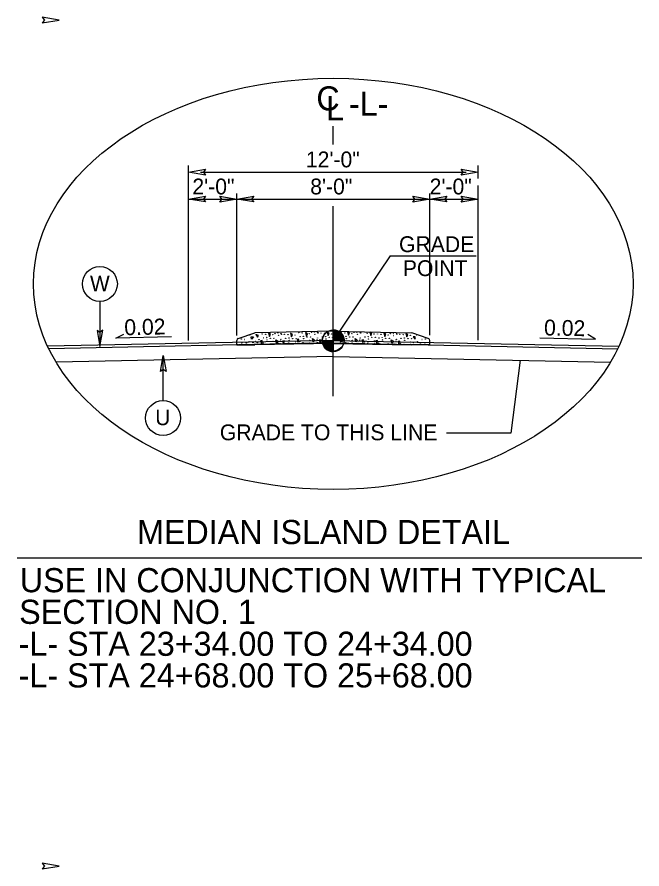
# Model space of a CAD drawing. Extents: x 1901718 to 1902220, y 193828 to 194187.
# Drawn here: x 1901932.98 to 1901958.87, y 194045.94 to 194081.24 of the extents above; entities that cross this region are included whole.
import ezdxf

# ---------------------------------------------------------------- set-up
doc = ezdxf.new("R2010")
doc.units = 0
for name, color, linetype in [('Old_Level_1', 7, 'Continuous'), ('Old_Level_11', 7, 'Continuous'), ('Old_Level_19', 7, 'Continuous'), ('Old_Level_2', 7, 'Continuous'), ('Old_Level_20', 7, 'Continuous'), ('Old_Level_3', 7, 'Continuous'), ('Prop Dimension', 7, 'Continuous'), ('Typical Curb CELL', 7, 'Continuous'), ('Typical Terminator CELL', 7, 'Continuous')]:
    doc.layers.add(name, color=color, linetype=linetype)

# ---------------------------------------------------------------- blocks, each defined once
blk = doc.blocks.new('TERMINATOR')
at = {"layer": 'Typical Terminator CELL'}
blk.add_lwpolyline([(-0.469, 0.081), (0, 0), (-0.471, -0.083), (-0.411, 0)], close=True, dxfattribs=at)

msp = doc.modelspace()

# ---------------------------------------------------------------- linework, layer by layer
at = {"layer": 'Old_Level_1'}
for p, q in [((1901946.083, 194075.955), (1901946.083, 194076.723)), ((1901946.083, 194065.532), (1901946.083, 194073.405)), ((1901946.083, 194067.838), (1901946.083, 194068.279)), ((1901946.083, 194067.828), (1901946.083, 194068.278)), ((1901946.083, 194067.838), (1901934.243, 194067.601)), ((1901937.074, 194067.936), (1901937.407, 194068.103)), ((1901939.378, 194067.984), (1901937.074, 194067.936)), ((1901945.633, 194067.828), (1901946.083, 194067.828)), ((1901945.642, 194067.838), (1901946.083, 194067.838)), ((1901946.082, 194067.397), (1901946.083, 194067.838)), ((1901946.083, 194067.838), (1901946.082, 194067.397)), ((1901946.082, 194067.378), (1901946.083, 194067.828)), ((1901946.083, 194067.828), (1901946.082, 194067.378)), ((1901946.083, 194067.838), (1901957.922, 194067.601)), ((1901946.524, 194067.838), (1901946.083, 194067.838)), ((1901946.533, 194067.828), (1901946.083, 194067.828)), ((1901954.646, 194067.941), (1901956.95, 194067.893)), ((1901956.95, 194067.893), (1901956.627, 194068.079)), ((1901946.083, 194067.734), (1901934.292, 194067.498)), ((1901946.083, 194067.734), (1901957.874, 194067.498)), ((1901946.083, 194067.172), (1901934.593, 194066.942)), ((1901946.083, 194067.172), (1901957.572, 194066.942))]:
    msp.add_line(p, q, dxfattribs=at)
for points in [[(1901946.087, 194068.279), (1901946.087, 194068.279), (1901946.087, 194067.838)], [(1901946.087, 194068.278), (1901946.087, 194068.278), (1901946.087, 194067.828)], [(1901946.096, 194068.279), (1901946.096, 194067.838)], [(1901946.096, 194068.278), (1901946.096, 194067.828)], [(1901946.104, 194068.278), (1901946.104, 194067.838)], [(1901946.105, 194068.277), (1901946.105, 194067.828)], [(1901946.113, 194068.278), (1901946.113, 194067.838)], [(1901946.114, 194068.277), (1901946.114, 194067.828)], [(1901946.122, 194068.277), (1901946.122, 194067.838)], [(1901946.123, 194068.276), (1901946.123, 194067.828)], [(1901946.131, 194068.276), (1901946.131, 194067.838)], [(1901946.132, 194068.275), (1901946.132, 194067.828)], [(1901946.14, 194068.275), (1901946.14, 194067.838)], [(1901946.141, 194068.274), (1901946.141, 194067.828)], [(1901946.149, 194068.274), (1901946.149, 194067.838)], [(1901946.15, 194068.273), (1901946.15, 194067.828)], [(1901946.157, 194068.273), (1901946.157, 194067.838)], [(1901946.159, 194068.272), (1901946.159, 194067.828)], [(1901946.166, 194068.271), (1901946.166, 194067.838)], [(1901946.168, 194068.27), (1901946.168, 194067.828)], [(1901946.175, 194068.269), (1901946.175, 194067.838)], [(1901946.177, 194068.268), (1901946.177, 194067.828)], [(1901946.184, 194068.267), (1901946.184, 194067.838)], [(1901946.186, 194068.266), (1901946.186, 194067.828)], [(1901946.193, 194068.265), (1901946.193, 194067.838)], [(1901946.195, 194068.264), (1901946.195, 194067.828)], [(1901946.201, 194068.262), (1901946.201, 194067.838)], [(1901946.204, 194068.261), (1901946.204, 194067.828)], [(1901946.21, 194068.26), (1901946.21, 194067.838)], [(1901946.213, 194068.259), (1901946.213, 194067.828)], [(1901946.219, 194068.257), (1901946.219, 194067.838)], [(1901946.222, 194068.256), (1901946.222, 194067.828)], [(1901946.228, 194068.254), (1901946.228, 194067.838)], [(1901946.231, 194068.253), (1901946.231, 194067.828)], [(1901946.237, 194068.251), (1901946.237, 194067.838)], [(1901946.24, 194068.25), (1901946.24, 194067.828)], [(1901946.246, 194068.247), (1901946.246, 194067.838)], [(1901946.249, 194068.246), (1901946.249, 194067.828)], [(1901946.254, 194068.243), (1901946.254, 194067.838)], [(1901946.258, 194068.242), (1901946.258, 194067.828)], [(1901946.263, 194068.239), (1901946.263, 194067.838)], [(1901946.267, 194068.238), (1901946.267, 194067.828)], [(1901946.272, 194068.236), (1901946.272, 194067.838)], [(1901946.276, 194068.234), (1901946.276, 194067.828)], [(1901946.281, 194068.232), (1901946.281, 194067.838)], [(1901946.285, 194068.23), (1901946.285, 194067.828)], [(1901946.29, 194068.227), (1901946.29, 194067.838)], [(1901946.294, 194068.225), (1901946.294, 194067.828)], [(1901946.298, 194068.222), (1901946.298, 194067.838)], [(1901946.303, 194068.22), (1901946.303, 194067.828)], [(1901946.307, 194068.217), (1901946.307, 194067.838)], [(1901946.312, 194068.215), (1901946.312, 194067.828)], [(1901946.316, 194068.212), (1901946.316, 194067.838)], [(1901946.321, 194068.21), (1901946.321, 194067.828)], [(1901946.325, 194068.206), (1901946.325, 194067.838)], [(1901946.33, 194068.204), (1901946.33, 194067.828)], [(1901946.334, 194068.2), (1901946.334, 194067.838)], [(1901946.339, 194068.198), (1901946.339, 194067.828)], [(1901946.343, 194068.193), (1901946.343, 194067.838)], [(1901946.348, 194068.191), (1901946.348, 194067.828)], [(1901946.351, 194068.188), (1901946.351, 194067.838)], [(1901946.357, 194068.185), (1901946.357, 194067.828)], [(1901946.36, 194068.181), (1901946.36, 194067.838)], [(1901945.635, 194067.828), (1901945.635, 194067.779)], [(1901945.644, 194067.838), (1901945.644, 194067.79)], [(1901945.644, 194067.828), (1901945.644, 194067.726)], [(1901945.653, 194067.838), (1901945.653, 194067.738)], [(1901945.653, 194067.828), (1901945.653, 194067.694)], [(1901945.661, 194067.838), (1901945.661, 194067.706)], [(1901945.662, 194067.828), (1901945.662, 194067.667)], [(1901945.67, 194067.838), (1901945.67, 194067.68)], [(1901945.671, 194067.828), (1901945.671, 194067.646)], [(1901945.679, 194067.838), (1901945.679, 194067.659)], [(1901945.68, 194067.828), (1901945.68, 194067.627)], [(1901945.688, 194067.838), (1901945.688, 194067.641)], [(1901945.689, 194067.828), (1901945.689, 194067.61)], [(1901945.697, 194067.838), (1901945.697, 194067.624)], [(1901945.698, 194067.828), (1901945.698, 194067.594)], [(1901945.706, 194067.838), (1901945.706, 194067.608)], [(1901945.707, 194067.828), (1901945.707, 194067.58)], [(1901945.714, 194067.838), (1901945.714, 194067.595)], [(1901945.716, 194067.828), (1901945.716, 194067.567)], [(1901945.723, 194067.838), (1901945.723, 194067.582)], [(1901945.725, 194067.828), (1901945.725, 194067.555)], [(1901945.732, 194067.838), (1901945.732, 194067.57)], [(1901945.734, 194067.828), (1901945.734, 194067.544)], [(1901945.741, 194067.838), (1901945.741, 194067.559)], [(1901945.743, 194067.828), (1901945.743, 194067.533)], [(1901945.75, 194067.838), (1901945.75, 194067.549)], [(1901945.752, 194067.828), (1901945.752, 194067.523)], [(1901945.758, 194067.838), (1901945.758, 194067.539)], [(1901945.761, 194067.828), (1901945.761, 194067.513)], [(1901945.767, 194067.838), (1901945.767, 194067.529)], [(1901945.77, 194067.828), (1901945.77, 194067.504)], [(1901945.776, 194067.838), (1901945.776, 194067.52)], [(1901945.779, 194067.828), (1901945.779, 194067.496)], [(1901945.785, 194067.838), (1901945.785, 194067.512)], [(1901945.788, 194067.828), (1901945.788, 194067.488)], [(1901945.794, 194067.838), (1901945.794, 194067.504)], [(1901945.797, 194067.828), (1901945.797, 194067.48)], [(1901945.803, 194067.838), (1901945.803, 194067.497)], [(1901945.806, 194067.828), (1901945.806, 194067.473)], [(1901945.811, 194067.838), (1901945.811, 194067.49)], [(1901945.815, 194067.828), (1901945.815, 194067.466)], [(1901945.82, 194067.838), (1901945.82, 194067.483)], [(1901945.824, 194067.828), (1901945.824, 194067.46)], [(1901945.829, 194067.838), (1901945.829, 194067.477)], [(1901945.833, 194067.828), (1901945.833, 194067.454)], [(1901945.838, 194067.838), (1901945.838, 194067.471)], [(1901945.842, 194067.828), (1901945.842, 194067.448)], [(1901945.847, 194067.838), (1901945.847, 194067.465)], [(1901945.851, 194067.828), (1901945.851, 194067.442)], [(1901945.856, 194067.838), (1901945.856, 194067.459)], [(1901945.86, 194067.828), (1901945.86, 194067.437)], [(1901945.864, 194067.838), (1901945.864, 194067.454)], [(1901945.869, 194067.828), (1901945.869, 194067.432)], [(1901945.873, 194067.838), (1901945.873, 194067.45)], [(1901945.878, 194067.828), (1901945.878, 194067.427)], [(1901945.882, 194067.838), (1901945.882, 194067.445)], [(1901945.887, 194067.828), (1901945.887, 194067.423)], [(1901945.891, 194067.838), (1901945.891, 194067.441)], [(1901945.896, 194067.828), (1901945.896, 194067.419)], [(1901945.9, 194067.838), (1901945.9, 194067.437)], [(1901945.905, 194067.828), (1901945.905, 194067.415)], [(1901945.908, 194067.838), (1901945.908, 194067.433)], [(1901945.914, 194067.828), (1901945.914, 194067.411)], [(1901945.917, 194067.838), (1901945.917, 194067.429)], [(1901945.923, 194067.828), (1901945.923, 194067.407)], [(1901945.926, 194067.838), (1901945.926, 194067.425)], [(1901945.932, 194067.828), (1901945.932, 194067.404)], [(1901945.935, 194067.838), (1901945.935, 194067.422)], [(1901945.941, 194067.828), (1901945.941, 194067.401)], [(1901945.944, 194067.838), (1901945.944, 194067.419)], [(1901945.95, 194067.828), (1901945.95, 194067.398)], [(1901945.953, 194067.838), (1901945.953, 194067.416)], [(1901945.959, 194067.828), (1901945.959, 194067.396)], [(1901945.961, 194067.838), (1901945.961, 194067.414)], [(1901945.968, 194067.828), (1901945.968, 194067.393)], [(1901945.97, 194067.838), (1901945.97, 194067.411)], [(1901945.977, 194067.828), (1901945.977, 194067.391)], [(1901945.979, 194067.838), (1901945.979, 194067.409)], [(1901945.986, 194067.828), (1901945.986, 194067.389)], [(1901945.988, 194067.838), (1901945.988, 194067.407)], [(1901945.995, 194067.828), (1901945.995, 194067.387)], [(1901945.997, 194067.838), (1901945.997, 194067.405)], [(1901946.004, 194067.828), (1901946.004, 194067.385)], [(1901946.005, 194067.838), (1901946.005, 194067.404)], [(1901946.013, 194067.828), (1901946.013, 194067.384)], [(1901946.014, 194067.838), (1901946.014, 194067.403)], [(1901946.022, 194067.828), (1901946.022, 194067.382)], [(1901946.023, 194067.838), (1901946.023, 194067.401)], [(1901946.031, 194067.828), (1901946.031, 194067.381)], [(1901946.032, 194067.838), (1901946.032, 194067.4)], [(1901946.04, 194067.828), (1901946.04, 194067.38)], [(1901946.041, 194067.838), (1901946.041, 194067.399)], [(1901946.049, 194067.828), (1901946.049, 194067.379)], [(1901946.05, 194067.838), (1901946.05, 194067.398)], [(1901946.058, 194067.838), (1901946.058, 194067.398)], [(1901946.058, 194067.828), (1901946.058, 194067.379)], [(1901946.067, 194067.838), (1901946.067, 194067.397)], [(1901946.067, 194067.828), (1901946.067, 194067.378)], [(1901946.076, 194067.838), (1901946.076, 194067.397), (1901946.076, 194067.397)], [(1901946.076, 194067.828), (1901946.076, 194067.378), (1901946.076, 194067.378)], [(1901946.366, 194068.178), (1901946.366, 194067.828)], [(1901946.369, 194068.173), (1901946.369, 194067.838)], [(1901946.375, 194068.17), (1901946.375, 194067.828)], [(1901946.378, 194068.165), (1901946.378, 194067.838)], [(1901946.384, 194068.162), (1901946.384, 194067.828)], [(1901946.387, 194068.157), (1901946.387, 194067.838)], [(1901946.393, 194068.154), (1901946.393, 194067.828)], [(1901946.395, 194068.148), (1901946.395, 194067.838)], [(1901946.402, 194068.145), (1901946.402, 194067.828)], [(1901946.404, 194068.139), (1901946.404, 194067.838)], [(1901946.411, 194068.136), (1901946.411, 194067.828)], [(1901946.413, 194068.13), (1901946.413, 194067.838)], [(1901946.42, 194068.126), (1901946.42, 194067.828)], [(1901946.422, 194068.119), (1901946.422, 194067.838)], [(1901946.429, 194068.115), (1901946.429, 194067.828)], [(1901946.431, 194068.108), (1901946.431, 194067.838)], [(1901946.438, 194068.104), (1901946.438, 194067.828)], [(1901946.44, 194068.096), (1901946.44, 194067.838)], [(1901946.447, 194068.092), (1901946.447, 194067.828)], [(1901946.448, 194068.084), (1901946.448, 194067.838)], [(1901946.456, 194068.079), (1901946.456, 194067.828)], [(1901946.457, 194068.07), (1901946.457, 194067.838)], [(1901946.465, 194068.065), (1901946.465, 194067.828)], [(1901946.466, 194068.055), (1901946.466, 194067.838)], [(1901946.474, 194068.05), (1901946.474, 194067.828)], [(1901946.475, 194068.04), (1901946.475, 194067.838)], [(1901946.483, 194068.034), (1901946.483, 194067.828)], [(1901946.484, 194068.021), (1901946.484, 194067.838)], [(1901946.492, 194068.015), (1901946.492, 194067.828)], [(1901946.493, 194068), (1901946.493, 194067.838)], [(1901946.501, 194067.994), (1901946.501, 194067.828)], [(1901946.501, 194067.976), (1901946.501, 194067.838)], [(1901946.51, 194067.969), (1901946.51, 194067.828)], [(1901946.51, 194067.945), (1901946.51, 194067.838)], [(1901946.519, 194067.938), (1901946.519, 194067.828)], [(1901946.519, 194067.9), (1901946.519, 194067.838)], [(1901946.528, 194067.892), (1901946.528, 194067.828)], [(1901953.827, 194067.02), (1901953.441, 194064.001), (1901950.774, 194064.001)]]:
    msp.add_lwpolyline(points, dxfattribs=at)
for centre, radius in [((1901946.082, 194067.828), 0.45), ((1901946.082, 194067.838), 0.441)]:
    msp.add_circle(centre, radius, dxfattribs=at)
for centre, radius, start, end in [((1901946.082, 194067.838), 0.441, 359.9905, 89.9905), ((1901946.082, 194067.828), 0.45, 359.9905, 89.9905), ((1901946.082, 194067.828), 0.45, 179.9905, 269.9905), ((1901946.082, 194067.838), 0.441, 179.9905, 269.9905)]:
    msp.add_arc(centre, radius, start, end, dxfattribs=at)
at = {"layer": 'Old_Level_11'}
for p, q in [((1901936.409, 194069.458), (1901936.409, 194067.584)), ((1901939.031, 194065.347), (1901939.031, 194067.221)), ((1901932.977, 194058.837), (1901958.875, 194058.837))]:
    msp.add_line(p, q, dxfattribs=at)
for points in [[(1901936.293, 194068.255), (1901936.409, 194067.584), (1901936.528, 194068.259), (1901936.409, 194068.173)], [(1901938.916, 194066.549), (1901939.031, 194067.221), (1901939.151, 194066.546), (1901939.031, 194066.631)]]:
    msp.add_lwpolyline(points, close=True, dxfattribs=at)
for centre in [(1901936.409, 194070.183), (1901939.031, 194064.621)]:
    msp.add_circle(centre, 0.725, dxfattribs=at)
at = {"layer": 'Old_Level_3'}
for q in [(1901946.083, 194067.838), (1901951.998, 194071.342)]:
    msp.add_line((1901948.434, 194071.342), q, dxfattribs=at)
at = {"layer": 'Prop Dimension'}
for p, q in [((1901940.083, 194067.843), (1901940.083, 194075.089)), ((1901952.083, 194074.55), (1901952.083, 194075.089)), ((1901940.583, 194074.814), (1901951.583, 194074.814)), ((1901952.083, 194067.85), (1901952.083, 194074.266)), ((1901942.083, 194068.047), (1901942.083, 194073.931)), ((1901950.083, 194068.055), (1901950.083, 194073.931)), ((1901940.083, 194073.699), (1901942.083, 194073.699)), ((1901942.083, 194073.699), (1901950.083, 194073.699)), ((1901950.083, 194073.699), (1901952.083, 194073.699))]:
    msp.add_line(p, q, dxfattribs=at)
at = {"layer": 'Typical Curb CELL'}
for p, q in [((1901946.083, 194068.219), (1901942.833, 194068.154)), ((1901945.831, 194068.186), (1901945.872, 194068.038)), ((1901945.913, 194068.128), (1901945.831, 194068.186)), ((1901946.083, 194068.219), (1901949.333, 194068.154)), ((1901946.677, 194068.202), (1901946.719, 194068.053)), ((1901946.76, 194068.144), (1901946.677, 194068.202)), ((1901947.597, 194068.186), (1901947.638, 194068.038)), ((1901947.679, 194068.128), (1901947.597, 194068.186)), ((1901942.083, 194067.831), (1901942.083, 194067.836)), ((1901942.083, 194067.654), (1901942.083, 194067.836)), ((1901942.147, 194067.925), (1901942.833, 194068.154)), ((1901942.686, 194067.982), (1901942.772, 194067.982)), ((1901942.69, 194067.896), (1901942.686, 194067.982)), ((1901942.772, 194067.982), (1901942.69, 194067.896)), ((1901942.977, 194068.044), (1901942.867, 194068.079)), ((1901942.867, 194068.079), (1901942.945, 194067.978)), ((1901942.945, 194067.978), (1901942.977, 194068.044)), ((1901943.138, 194067.834), (1901943.066, 194067.821)), ((1901943.103, 194067.712), (1901943.138, 194067.834)), ((1901943.396, 194068.15), (1901943.437, 194068.001)), ((1901943.478, 194068.092), (1901943.396, 194068.15)), ((1901943.437, 194068.001), (1901943.478, 194068.092)), ((1901943.703, 194067.861), (1901943.793, 194067.812)), ((1901943.735, 194067.731), (1901943.703, 194067.861)), ((1901944.315, 194068.134), (1901944.356, 194067.986)), ((1901944.397, 194068.076), (1901944.315, 194068.134)), ((1901944.356, 194067.986), (1901944.397, 194068.076)), ((1901944.654, 194067.886), (1901944.582, 194067.873)), ((1901944.582, 194067.873), (1901944.619, 194067.764)), ((1901944.619, 194067.764), (1901944.654, 194067.886)), ((1901944.934, 194068.168), (1901944.976, 194068.019)), ((1901945.016, 194068.11), (1901944.934, 194068.168)), ((1901944.976, 194068.019), (1901945.016, 194068.11)), ((1901945.219, 194067.913), (1901945.309, 194067.864)), ((1901945.251, 194067.783), (1901945.219, 194067.913)), ((1901945.309, 194067.864), (1901945.251, 194067.783)), ((1901945.574, 194067.871), (1901945.501, 194067.857)), ((1901945.501, 194067.857), (1901945.538, 194067.748)), ((1901945.538, 194067.748), (1901945.574, 194067.871)), ((1901945.872, 194068.038), (1901945.913, 194068.128)), ((1901946.42, 194067.886), (1901946.348, 194067.873)), ((1901946.348, 194067.873), (1901946.385, 194067.764)), ((1901946.385, 194067.764), (1901946.42, 194067.886)), ((1901946.719, 194068.053), (1901946.76, 194068.144)), ((1901946.985, 194067.913), (1901947.075, 194067.864)), ((1901947.017, 194067.783), (1901946.985, 194067.913)), ((1901947.075, 194067.864), (1901947.017, 194067.783)), ((1901947.339, 194067.871), (1901947.267, 194067.857)), ((1901947.267, 194067.857), (1901947.304, 194067.748)), ((1901947.304, 194067.748), (1901947.339, 194067.871)), ((1901947.638, 194068.038), (1901947.679, 194068.128)), ((1901947.919, 194067.832), (1901947.847, 194067.818)), ((1901947.883, 194067.709), (1901947.919, 194067.832)), ((1901948.176, 194068.148), (1901948.218, 194067.998)), ((1901948.258, 194068.089), (1901948.176, 194068.148)), ((1901948.218, 194067.998), (1901948.258, 194068.089)), ((1901948.484, 194067.859), (1901948.574, 194067.809)), ((1901948.516, 194067.728), (1901948.484, 194067.859)), ((1901949.095, 194068.132), (1901949.137, 194067.983)), ((1901949.177, 194068.073), (1901949.095, 194068.132)), ((1901949.137, 194067.983), (1901949.177, 194068.073)), ((1901950.019, 194067.925), (1901949.333, 194068.154)), ((1901949.48, 194067.982), (1901949.394, 194067.982)), ((1901949.394, 194067.982), (1901949.475, 194067.896)), ((1901949.475, 194067.896), (1901949.48, 194067.982)), ((1901950.083, 194067.831), (1901950.083, 194067.836)), ((1901950.083, 194067.654), (1901950.083, 194067.836)), ((1901942.083, 194067.654), (1901942.833, 194067.654)), ((1901946.083, 194067.719), (1901942.833, 194067.654)), ((1901943.066, 194067.821), (1901943.103, 194067.712)), ((1901943.793, 194067.812), (1901943.735, 194067.731)), ((1901944.058, 194067.819), (1901943.985, 194067.805)), ((1901943.985, 194067.805), (1901944.022, 194067.696)), ((1901944.022, 194067.696), (1901944.058, 194067.819)), ((1901946.083, 194067.719), (1901949.333, 194067.654)), ((1901947.847, 194067.818), (1901947.883, 194067.709)), ((1901948.574, 194067.809), (1901948.516, 194067.728)), ((1901948.838, 194067.816), (1901948.766, 194067.802)), ((1901948.766, 194067.802), (1901948.802, 194067.693)), ((1901948.802, 194067.693), (1901948.838, 194067.816)), ((1901950.083, 194067.654), (1901949.333, 194067.654))]:
    msp.add_line(p, q, dxfattribs=at)
for centre in [(1901945.301, 194068.187), (1901945.436, 194068.175), (1901947.202, 194068.175), (1901942.27, 194067.901), (1901942.406, 194067.878), (1901942.623, 194068.068), (1901943.004, 194067.867), (1901943.134, 194068.105), (1901943.193, 194067.947), (1901943.283, 194068.091), (1901943.328, 194067.96), (1901943.342, 194067.865), (1901943.478, 194067.929), (1901943.572, 194068.073), (1901943.622, 194067.933), (1901943.663, 194068.119), (1901943.785, 194068.146), (1901943.807, 194068.046), (1901943.913, 194067.891), (1901943.92, 194068.123), (1901943.936, 194068.094), (1901944.053, 194068.089), (1901944.112, 194067.931), (1901944.202, 194068.076), (1901944.248, 194067.945), (1901944.261, 194067.85), (1901944.397, 194067.913), (1901944.492, 194068.058), (1901944.541, 194067.918), (1901944.65, 194068.157), (1901944.709, 194067.999), (1901944.799, 194068.143), (1901944.845, 194068.012), (1901944.858, 194067.917), (1901944.994, 194067.981), (1901945.088, 194068.125), (1901945.107, 194067.85), (1901945.138, 194067.985), (1901945.179, 194068.171), (1901945.323, 194068.098), (1901945.414, 194067.863), (1901945.429, 194067.943), (1901945.452, 194068.146), (1901945.569, 194068.141), (1901945.628, 194067.983), (1901945.718, 194068.128), (1901945.764, 194067.997), (1901945.777, 194067.902), (1901945.913, 194067.965), (1901946.008, 194068.11), (1901946.026, 194067.834), (1901946.057, 194067.97), (1901946.416, 194068.157), (1901946.475, 194067.999), (1901946.565, 194068.143), (1901946.61, 194068.012), (1901946.624, 194067.917), (1901946.759, 194067.981), (1901946.854, 194068.125), (1901946.872, 194067.85), (1901946.904, 194067.985), (1901946.945, 194068.171), (1901947.06, 194068.172), (1901947.089, 194068.098), (1901947.179, 194067.863), (1901947.195, 194067.943), (1901947.218, 194068.146), (1901947.335, 194068.141), (1901947.394, 194067.983), (1901947.484, 194068.128), (1901947.529, 194067.997), (1901947.543, 194067.902), (1901947.679, 194067.965), (1901947.773, 194068.11), (1901947.791, 194067.834), (1901947.823, 194067.97), (1901947.915, 194068.102), (1901947.973, 194067.944), (1901948.064, 194068.089), (1901948.109, 194067.958), (1901948.123, 194067.863), (1901948.258, 194067.926), (1901948.353, 194068.071), (1901948.403, 194067.931), (1901948.443, 194068.116), (1901948.565, 194068.143), (1901948.588, 194068.044), (1901948.694, 194067.888), (1901948.701, 194068.121), (1901948.716, 194068.091), (1901948.834, 194068.087), (1901948.893, 194067.929), (1901948.983, 194068.073), (1901949.028, 194067.942), (1901949.042, 194067.847), (1901949.177, 194067.911), (1901949.272, 194068.055), (1901949.322, 194067.915), (1901949.543, 194068.068), (1901949.76, 194067.878), (1901949.896, 194067.901), (1901942.099, 194067.675), (1901942.288, 194067.738), (1901942.478, 194067.733), (1901942.595, 194067.783), (1901942.758, 194067.743), (1901942.85, 194067.795), (1901942.935, 194067.75), (1901943.17, 194067.734), (1901943.315, 194067.694), (1901943.577, 194067.676), (1901943.59, 194067.798), (1901943.821, 194067.723), (1901943.898, 194067.811), (1901943.898, 194067.71), (1901944.089, 194067.719), (1901944.234, 194067.73), (1901944.496, 194067.712), (1901944.51, 194067.782), (1901944.686, 194067.786), (1901944.831, 194067.746), (1901945.093, 194067.728), (1901945.337, 194067.723), (1901945.414, 194067.762), (1901945.606, 194067.771), (1901945.75, 194067.73), (1901946.012, 194067.712), (1901946.452, 194067.786), (1901946.597, 194067.746), (1901946.859, 194067.728), (1901947.103, 194067.723), (1901947.179, 194067.71), (1901947.371, 194067.771), (1901947.516, 194067.73), (1901947.778, 194067.712), (1901947.951, 194067.732), (1901948.095, 194067.691), (1901948.357, 194067.7), (1901948.371, 194067.795), (1901948.601, 194067.695), (1901948.678, 194067.809), (1901948.678, 194067.682), (1901948.87, 194067.716), (1901949.015, 194067.676), (1901949.277, 194067.684), (1901949.29, 194067.78), (1901949.408, 194067.743), (1901949.57, 194067.783), (1901949.688, 194067.733), (1901949.877, 194067.738), (1901950.067, 194067.675)]:
    msp.add_circle(centre, 0.00635, dxfattribs=at)
for centre, start, end in [((1901942.177, 194067.836), 108.435, 180), ((1901949.989, 194067.836), 360, 71.565)]:
    msp.add_arc(centre, 0.0937, start, end, dxfattribs=at)
msp.add_ellipse((1901946.083, 194070.183), major_axis=(12.424, 0), ratio=0.68563, dxfattribs=at)

# ---------------------------------------------------------------- block references
at = {"layer": 'Old_Level_1', "xscale": 1.5, "yscale": -1.5}
for p in [(1901934.727, 194081.116), (1901934.727, 194046.059)]:
    msp.add_blockref('TERMINATOR', p, dxfattribs=at)
at = {"layer": 'Prop Dimension', "xscale": 1.5, "yscale": 1.5, "rotation": 180}
for p in [(1901940.083, 194074.814), (1901940.083, 194073.699), (1901942.083, 194073.699), (1901950.083, 194073.699)]:
    msp.add_blockref('TERMINATOR', p, dxfattribs=at)
at = {"layer": 'Prop Dimension', "xscale": 1.5, "yscale": 1.5}
for p in [(1901952.083, 194074.814), (1901942.083, 194073.699), (1901950.083, 194073.699), (1901952.083, 194073.699)]:
    msp.add_blockref('TERMINATOR', p, dxfattribs=at)

# ---------------------------------------------------------------- texts
at = {"layer": 'Old_Level_1'}
msp.add_text('GRADE TO THIS LINE', height=0.656, dxfattribs=at).set_placement((1901941.381, 194063.702))
at = {"layer": 'Old_Level_19'}
for s, p in [('MEDIAN ISLAND DETAIL', (1901937.95, 194059.4)), ('USE IN CONJUNCTION WITH TYPICAL ', (1901933.091, 194057.405)), ('SECTION NO. 1', (1901933.066, 194056.094)), ('-L- STA 23+34.00 TO 24+34.00', (1901933.047, 194054.77)), ('-L- STA 24+68.00 TO 25+68.00', (1901933.047, 194053.459))]:
    msp.add_text(s, height=1, dxfattribs=at).set_placement(p)
at = {"layer": 'Old_Level_2'}
msp.add_text('C', height=1, dxfattribs=at).set_placement((1901945.381, 194077.369))
for s, height, rotation, p in [('-L-', 1, 359.9469, (1901946.732, 194077.148)), ('L', 1, 359.9469, (1901945.783, 194076.965)), ('0.02', 0.656, 1.1916, (1901937.429, 194068.055)), ('0.02', 0.656, 358.8084, (1901954.812, 194068.049))]:
    msp.add_text(s, height=height, rotation=rotation, dxfattribs=at).set_placement(p)
at = {"layer": 'Old_Level_20'}
for s, p in [('W', (1901936, 194069.877)), ('U', (1901938.704, 194064.328))]:
    msp.add_text(s, height=0.649, dxfattribs=at).set_placement(p)
at = {"layer": 'Old_Level_3'}
for s, p in [('GRADE', (1901948.807, 194071.5)), ('POINT', (1901948.965, 194070.506))]:
    msp.add_text(s, height=0.656, dxfattribs=at).set_placement(p)
at = {"layer": 'Prop Dimension'}
for s, p in [('12\'-0" ', (1901944.946, 194075.012)), ('2\'-0" ', (1901940.243, 194073.891)), ('8\'-0" ', (1901945.127, 194073.891)), ('2\'-0" ', (1901950.076, 194073.891))]:
    msp.add_text(s, height=0.656, dxfattribs=at).set_placement(p)

doc.saveas('drawing.dxf')
